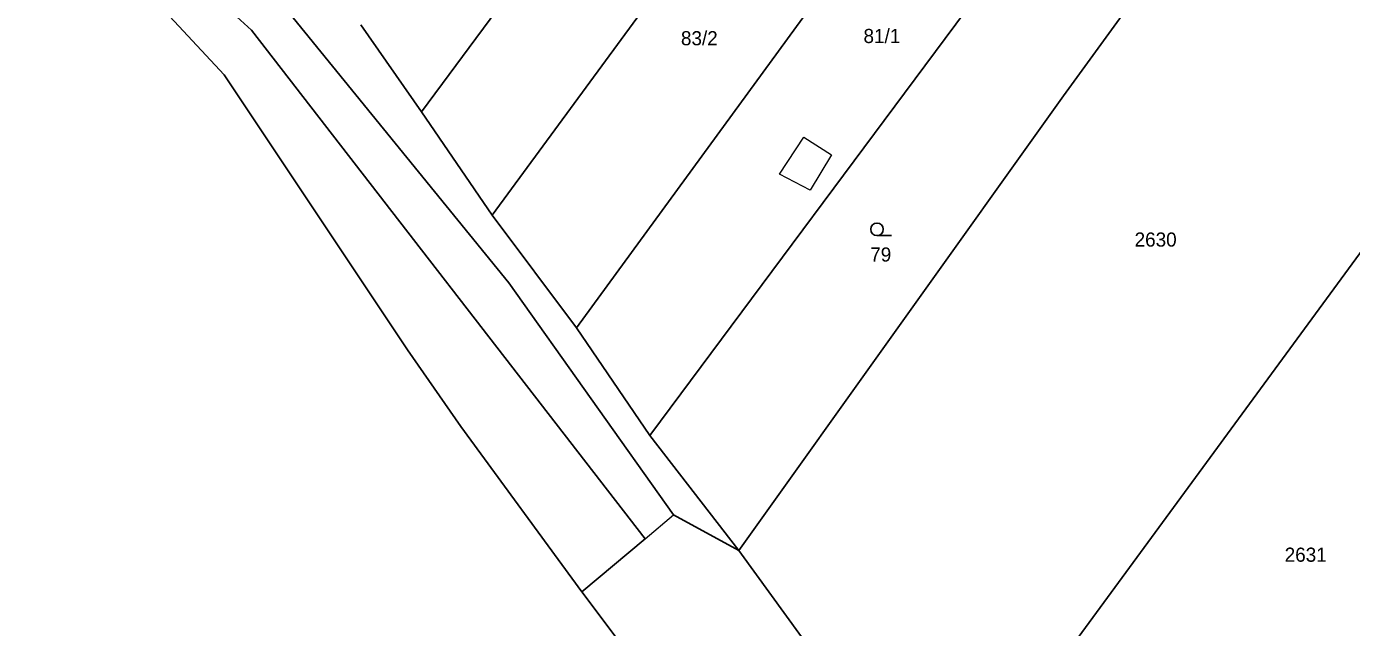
# Model space of a CAD drawing. Extents: x -606517 to -602431, y -1183120 to -1179397.
# Drawn here: x -605278.3 to -605119, y -1181219.7 to -1181147.4 of the extents above; entities that cross this region are included whole.
import ezdxf

# ---------------------------------------------------------------- set-up
doc = ezdxf.new("R2010")
doc.units = 0
doc.header["$LTSCALE"] = 0.68
for name, color, linetype, lineweight in [('1', 7, 'Continuous', 25), ('3', 7, 'Continuous', 25), ('4', 7, 'Continuous', 13)]:
    doc.layers.add(name, color=color, linetype=linetype, lineweight=lineweight)
doc.layers.add('2', color=7, linetype='Continuous')

msp = doc.modelspace()

# ---------------------------------------------------------------- linework, layer by layer
at = {"layer": '1'}
for p, q in [((-605179.23, -1181111.29), (-605222.31, -1181170.1)), ((-605212.18, -1181183.65), (-605166.69, -1181121.29)), ((-605251.29, -1181147.85), (-605278.34, -1181122.84)), ((-605158.46, -1181136.18), (-605203.38, -1181196.61)), ((-605267.62, -1181139.17), (-605254.57, -1181153.22)), ((-605247.67, -1181144.62), (-605220.34, -1181178.24)), ((-605230.84, -1181157.66), (-605221.78, -1181145.44)), ((-605145.9, -1181145.15), (-605153.62, -1181155.73)), ((-605203.94, -1181209.04), (-605251.29, -1181147.85)), ((-605230.84, -1181157.66), (-605238.13, -1181147.19)), ((-605168.54, -1181243.67), (-605098.83, -1181148.6)), ((-605254.57, -1181153.22), (-605232.52, -1181186.29)), ((-605153.62, -1181155.73), (-605192.67, -1181210.46)), ((-605222.31, -1181170.1), (-605230.84, -1181157.66)), ((-605212.18, -1181183.65), (-605222.31, -1181170.1)), ((-605220.34, -1181178.24), (-605200.51, -1181206.15)), ((-605203.38, -1181196.61), (-605212.18, -1181183.65)), ((-605232.52, -1181186.29), (-605226.08, -1181195.52)), ((-605226.08, -1181195.52), (-605211.55, -1181215.45)), ((-605192.67, -1181210.46), (-605203.38, -1181196.61)), ((-605200.51, -1181206.15), (-605192.67, -1181210.46)), ((-605211.55, -1181215.45), (-605203.94, -1181209.04)), ((-605192.67, -1181210.46), (-605168.54, -1181243.67)), ((-605189.02, -1181245.37), (-605211.55, -1181215.45))]:
    msp.add_line(p, q, dxfattribs=at)
at = {"layer": '3'}
msp.add_line((-605176.033, -1181172.55), (-605174.283, -1181172.55), dxfattribs=at)
msp.add_circle((-605176.0329, -1181171.7998), 0.75, dxfattribs=at)
at = {"layer": '4'}
for p, q in [((-605187.75, -1181165.16), (-605184.83, -1181160.7)), ((-605184.83, -1181160.7), (-605181.5, -1181162.82)), ((-605181.5, -1181162.82), (-605184.08, -1181167.1)), ((-605184.08, -1181167.1), (-605187.75, -1181165.16)), ((-605203.94, -1181209.04), (-605200.51, -1181206.15))]:
    msp.add_line(p, q, dxfattribs=at)

# ---------------------------------------------------------------- texts
at = {"layer": '2'}
for s, p in [('83/2', (-605199.62, -1181149.655)), ('81/1', (-605177.66, -1181149.385)), ('2630', (-605145.05, -1181173.885)), ('79', (-605176.85, -1181175.685)), ('2631', (-605127, -1181211.815))]:
    msp.add_text(s, height=1.7, dxfattribs=at).set_placement(p)

doc.saveas('drawing.dxf')
